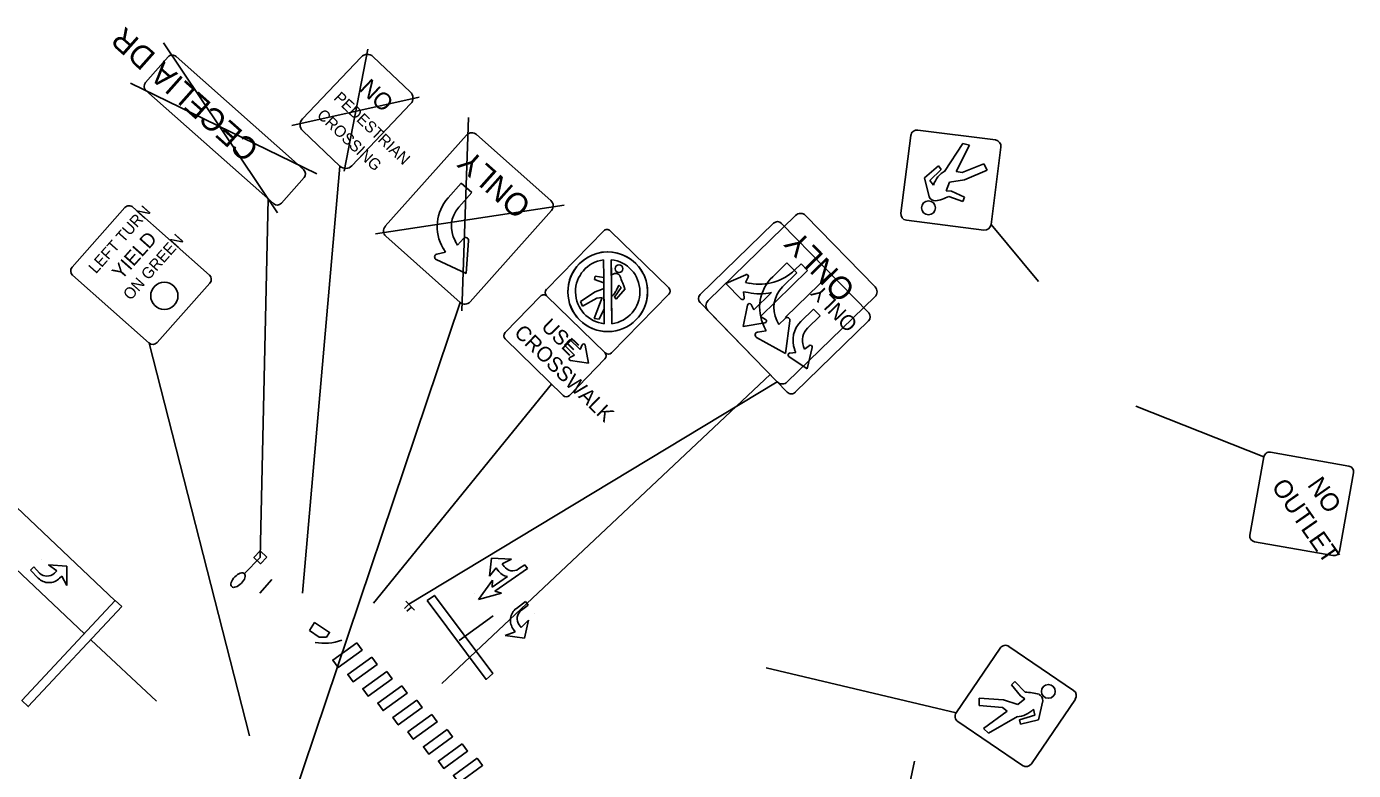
# Model space of a CAD drawing. Extents: x 1481212 to 1485683, y 378085 to 388655.
# Drawn here: x 1481389 to 1481680.9, y 378237 to 378400.7 of the extents above; entities that cross this region are included whole.
import ezdxf

# ---------------------------------------------------------------- set-up
doc = ezdxf.new("R2010")
doc.units = 0
for name, color, linetype in [('LT_X_Luminaires', 7, 'Continuous'), ('RS_Raster1', 7, 'Continuous'), ('RW_X_CL_100_Bearings', 7, 'Continuous'), ('RW_X_CL_100_Curve_Data', 7, 'Continuous'), ('RW_X_CL_100_Distances', 7, 'Continuous'), ('RW_X_CL_500_Cardinal_Points', 7, 'Continuous'), ('RW_X_CL_500_Distances', 7, 'Continuous'), ('RW_X_CL_500_Stations', 7, 'Continuous'), ('SC_Scratch1', 7, 'Continuous'), ('SC_Scratch15', 7, 'Continuous'), ('SC_Scratch8', 7, 'Continuous'), ('SN_P_Signs', 7, 'Continuous')]:
    doc.layers.add(name, color=color, linetype=linetype)

msp = doc.modelspace()

# ---------------------------------------------------------------- linework, layer by layer
at = {"layer": 'LT_X_Luminaires'}
msp.add_line((1481440.39, 378283.91), (1481436.89, 378280.33), dxfattribs=at)
msp.add_lwpolyline([(1481441.8, 378283.93), (1481440.4, 378282.5), (1481438.97, 378283.89), (1481440.37, 378285.32)], close=True, dxfattribs=at)
msp.add_ellipse((1481435.5, 378278.9), major_axis=(-1.4, -1.43), ratio=0.5, dxfattribs=at)
at = {"layer": 'RS_Raster1'}
for points in [[(1481461.59, 378265.13), (1481462.77, 378263.51), (1481457.5, 378259.69), (1481456.33, 378261.31)], [(1481464.9, 378261.96), (1481466.07, 378260.34), (1481460.81, 378256.53), (1481459.63, 378258.15)], [(1481468.2, 378258.8), (1481469.37, 378257.18), (1481464.11, 378253.37), (1481462.94, 378254.99)], [(1481471.5, 378255.63), (1481472.68, 378254.01), (1481467.41, 378250.2), (1481466.24, 378251.82)], [(1481474.81, 378252.47), (1481475.98, 378250.85), (1481470.72, 378247.04), (1481469.54, 378248.66)], [(1481478.11, 378249.31), (1481479.28, 378247.69), (1481474.02, 378243.87), (1481472.85, 378245.49)], [(1481481.52, 378246.04), (1481482.69, 378244.42), (1481477.43, 378240.61), (1481476.26, 378242.23)], [(1481484.82, 378242.88), (1481486, 378241.26), (1481480.73, 378237.45), (1481479.56, 378239.07)], [(1481488.13, 378239.72), (1481489.3, 378238.1), (1481484.04, 378234.28), (1481482.86, 378235.9)]]:
    msp.add_lwpolyline(points, close=True, dxfattribs=at)
at = {"layer": 'RW_X_CL_100_Bearings'}
msp.add_line((1481401.7, 378267.11), (1481366.27, 378300.56), dxfattribs=at)
at = {"layer": 'RW_X_CL_100_Curve_Data'}
for p, q in [((1481590.91, 378368.86), (1481594.96, 378375)), ((1481596.38, 378374.6), (1481593.48, 378368.85)), ((1481594.96, 378375), (1481596.38, 378374.6)), ((1481457.89, 378370.04), (1481449.67, 378276.05)), ((1481586.49, 378367.44), (1481589.59, 378370.09)), ((1481590.19, 378369.31), (1481587.68, 378366.86)), ((1481589.59, 378370.09), (1481590.19, 378369.31)), ((1481593.48, 378368.85), (1481594.78, 378368.6)), ((1481594.78, 378368.6), (1481599.53, 378370.53)), ((1481600.27, 378369.1), (1481595.29, 378366.99)), ((1481599.53, 378370.53), (1481600.27, 378369.1)), ((1481587.54, 378363.25), (1481586.49, 378367.44)), ((1481587.68, 378366.86), (1481588.48, 378365.83)), ((1481592.02, 378366.47), (1481591.25, 378364.62)), ((1481595.29, 378366.99), (1481592.02, 378366.47)), ((1481442.09, 378362.83), (1481440.37, 378283.9)), ((1481591.25, 378364.62), (1481592.43, 378364.53)), ((1481594.94, 378362.22), (1481591.87, 378363.34)), ((1481592.43, 378364.53), (1481595.27, 378363.22)), ((1481595.27, 378363.22), (1481594.94, 378362.22)), ((1481601.15, 378357.16), (1481611.55, 378344.64)), ((1481633.02, 378317.18), (1481661.17, 378306.04)), ((1481593.48, 378249.71), (1481551.67, 378259.6)), ((1481605.65, 378255.87), (1481606.39, 378256.62)), ((1481607.59, 378253.42), (1481605.65, 378255.87)), ((1481606.39, 378256.62), (1481608.62, 378254.22)), ((1481598.54, 378251.29), (1481598.53, 378252.9)), ((1481598.53, 378252.9), (1481603.92, 378252.52)), ((1481603.65, 378250.85), (1481598.54, 378251.29)), ((1481603.92, 378252.52), (1481607.07, 378251.5)), ((1481607.07, 378251.5), (1481608.6, 378252.8)), ((1481608.6, 378252.8), (1481607.59, 378253.42)), ((1481612.53, 378252.34), (1481611.56, 378248.13)), ((1481599.5, 378246.23), (1481604.69, 378250.04)), ((1481606.98, 378248.87), (1481600.58, 378245.23)), ((1481604.69, 378250.04), (1481603.65, 378250.85)), ((1481607.41, 378248.14), (1481610.77, 378249.19)), ((1481610.77, 378249.19), (1481610.52, 378250.47)), ((1481600.58, 378245.23), (1481599.5, 378246.23)), ((1481607.6, 378247.17), (1481607.41, 378248.14)), ((1481611.56, 378248.13), (1481607.6, 378247.17))]:
    msp.add_line(p, q, dxfattribs=at)
for points in [[(1481449.91, 378369.26), (1481421.87, 378394.15)], [(1481415.13, 378388.44), (1481420.11, 378394.05)], [(1481462.57, 378394.03), (1481449.66, 378380.43)], [(1481473.38, 378386.36), (1481465.22, 378394.1)], [(1481415.23, 378386.68), (1481443.27, 378361.78)], [(1481460.54, 378370.11), (1481473.45, 378383.71)], [(1481449.73, 378377.78), (1481457.89, 378370.04)], [(1481581.31, 378359.69), (1481583.48, 378376.75)], [(1481585.05, 378377.96), (1481602.11, 378375.79)], [(1481603.32, 378374.23), (1481601.15, 378357.16)], [(1481445.04, 378361.88), (1481450.02, 378367.49)], [(1481599.58, 378355.95), (1481582.52, 378358.12)], [(1481662.62, 378307.05), (1481679.84, 378303.98)], [(1481658.1, 378288.81), (1481661.17, 378306.04)], [(1481680.86, 378302.53), (1481677.79, 378285.3)], [(1481676.34, 378284.29), (1481659.11, 378287.36)], [(1481593.48, 378249.71), (1481603.15, 378263.93)], [(1481605.09, 378264.31), (1481619.32, 378254.64)], [(1481619.69, 378252.69), (1481610.02, 378238.47)], [(1481608.08, 378238.1), (1481593.85, 378247.76)]]:
    msp.add_lwpolyline(points, dxfattribs=at)
for centre in [(1481587.38, 378360.85), (1481613.75, 378254.41)]:
    msp.add_circle(centre, 1.52, dxfattribs=at)
for centre, radius, start, end in [((1481421.04, 378393.22), 1.25, 48.4, 138.4), ((1481463.93, 378392.74), 1.88, 46.5, 136.5), ((1481416.06, 378387.61), 1.25, 138.4, 228.4), ((1481472.09, 378385), 1.88, 316.5, 46.5), ((1481451.02, 378379.14), 1.88, 136.5, 226.5), ((1481584.87, 378376.57), 1.4, 82.7457, 172.7457), ((1481601.93, 378374.4), 1.4, 352.7457, 82.7457), ((1481449.08, 378368.32), 1.25, 318.4, 48.4), ((1481459.18, 378371.4), 1.88, 226.5, 316.5), ((1481593.84, 378364.07), 5.64, 119.5959, 161.8067), ((1481588.91, 378363.86), 1.5, 203.9899, 270.2407), ((1481587.35, 378371.92), 9.69, 279.2869, 297.7774), ((1481444.1, 378362.71), 1.25, 228.4, 318.4), ((1481582.7, 378359.51), 1.4, 172.7457, 262.7457), ((1481599.76, 378357.34), 1.4, 262.7457, 352.7457), ((1481662.4, 378305.82), 1.25, 79.9, 169.9), ((1481679.63, 378302.75), 1.25, 349.9, 79.9), ((1481659.33, 378288.59), 1.25, 169.9, 259.9), ((1481676.56, 378285.52), 1.25, 259.9, 349.9), ((1481604.31, 378263.15), 1.4, 55.8, 145.8), ((1481608.76, 378244.53), 9.69, 72.3411, 90.8317), ((1481618.53, 378253.48), 1.4, 325.8, 55.8), ((1481611.03, 378252.42), 1.5, 357.0441, 63.295), ((1481594.64, 378248.92), 1.4, 145.8, 235.8), ((1481606.54, 378254.47), 5.64, 272.6502, 314.8609), ((1481608.87, 378239.25), 1.4, 235.8, 325.8)]:
    msp.add_arc(centre, radius, start, end, dxfattribs=at)
at = {"layer": 'RW_X_CL_100_Distances'}
for p, q in [((1481392.21, 378283.43), (1481392.21, 378283.43)), ((1481490.83, 378279.78), (1481491.23, 378283.7)), ((1481491.23, 378283.7), (1481495.64, 378283.51)), ((1481495.64, 378283.51), (1481493.61, 378282.51)), ((1481497.92, 378283.26), (1481497.92, 378283.26)), ((1481390.54, 378281.8), (1481389.82, 378281.1)), ((1481389.82, 378281.1), (1481391.55, 378279.33)), ((1481391.84, 378280.46), (1481390.54, 378281.8)), ((1481397.82, 378281.97), (1481393.78, 378282.28)), ((1481393.78, 378282.28), (1481395.59, 378280.91)), ((1481395.59, 378280.91), (1481395.08, 378280.42)), ((1481397.79, 378277.7), (1481397.82, 378281.97)), ((1481492.29, 378281.6), (1481490.83, 378279.78)), ((1481499.15, 378281.48), (1481491.95, 378276.5)), ((1481492.67, 378281.05), (1481492.29, 378281.6)), ((1481493.61, 378282.51), (1481494.01, 378281.93)), ((1481497.2, 378281.35), (1481498.58, 378282.3)), ((1481498.58, 378282.3), (1481499.15, 378281.48)), ((1481396.23, 378279.3), (1481396.7, 378279.77)), ((1481396.7, 378279.77), (1481397.79, 378277.7)), ((1481397.79, 378277.7), (1481397.79, 378277.7)), ((1481488.38, 378274.64), (1481491.5, 378278.91)), ((1481491.5, 378278.91), (1481491.39, 378277.32)), ((1481487.43, 378276.01), (1481487.43, 378276.01)), ((1481493.48, 378276.05), (1481488.38, 378274.64)), ((1481491.95, 378276.5), (1481493.48, 378276.05)), ((1481498.71, 378274.16), (1481496.72, 378272.68)), ((1481497.82, 378272.25), (1481499.31, 378273.36)), ((1481499.31, 378273.36), (1481498.71, 378274.16)), ((1481497.77, 378268.47), (1481497.35, 378269.03)), ((1481499.36, 378270.08), (1481497.77, 378268.47)), ((1481498.52, 378266.12), (1481499.36, 378270.08)), ((1481500.7, 378271.49), (1481500.7, 378271.49)), ((1481496.49, 378267.51), (1481494.29, 378266.71)), ((1481494.29, 378266.71), (1481494.29, 378266.71)), ((1481494.29, 378266.71), (1481498.52, 378266.12)), ((1481496.09, 378268.05), (1481496.49, 378267.51))]:
    msp.add_line(p, q, dxfattribs=at)
msp.add_lwpolyline([(1481491.39, 378277.32), (1481494.76, 378279.66)], dxfattribs=at)
for centre, radius, start, end in [((1481393.48, 378282.07), 2.3, 224.2542, 314.2542), ((1481495.4, 378282.88), 3.28, 213.7589, 258.7139), ((1481495.9, 378283.24), 2.3, 214.6674, 304.6674), ((1481393.9, 378281.62), 3.28, 224.2542, 315.1627), ((1481498.69, 378270.05), 3.28, 126.7226, 217.6311), ((1481499.19, 378270.41), 2.3, 126.7226, 216.7226)]:
    msp.add_arc(centre, radius, start, end, dxfattribs=at)
at = {"layer": 'RW_X_CL_500_Cardinal_Points'}
msp.add_line((1481440.31, 378276.01), (1481442.89, 378279.07), dxfattribs=at)
msp.add_lwpolyline([(1481451.19, 378267.78), (1481452.32, 378269.55), (1481455.64, 378267.39), (1481454.95, 378266.33), (1481453.36, 378266.34)], close=True, dxfattribs=at)
msp.add_arc((1481454.46, 378276.11), 11.11, 259.501, 290.3578, dxfattribs=at)
at = {"layer": 'RW_X_CL_500_Distances'}
msp.add_line((1481373.57, 378307.38), (1481408.46, 378274.35), dxfattribs=at)
at = {"layer": 'RW_X_CL_500_Stations'}
for points in [[(1481477.11, 378274.42), (1481478.7, 378275.55), (1481491.54, 378258.34), (1481490.05, 378257.05)], [(1481409.9, 378273.06), (1481408.49, 378274.38), (1481387.93, 378252.37), (1481389.34, 378251.05)]]:
    msp.add_lwpolyline(points, close=True, dxfattribs=at)
at = {"layer": 'SC_Scratch1'}
msp.add_line((1481484.16, 378265.63), (1481491.62, 378271.03), dxfattribs=at)
at = {"layer": 'SC_Scratch15'}
for p, q in [((1481484.73, 378338.16), (1481486.22, 378380.72)), ((1481484.6, 378366.3), (1481481.69, 378363.04)), ((1481486.94, 378364.23), (1481484.6, 378366.3)), ((1481484.03, 378360.96), (1481486.94, 378364.23)), ((1481465.75, 378355.11), (1481507.23, 378361.42)), ((1481483.8, 378352.66), (1481483.29, 378353.51)), ((1481485.09, 378354.09), (1481483.8, 378352.66)), ((1481485.68, 378346.37), (1481486.18, 378353.63)), ((1481481.1, 378351.07), (1481479.22, 378350.63)), ((1481480.6, 378351.93), (1481481.1, 378351.07)), ((1481479.1, 378349.46), (1481485.68, 378346.37)), ((1481517.57, 378349.42), (1481517.74, 378335.34)), ((1481556.24, 378348.74), (1481553.11, 378345.69)), ((1481558.42, 378346.5), (1481556.24, 378348.74)), ((1481514.03, 378345.78), (1481513.91, 378345.08)), ((1481514.03, 378345.78), (1481513.91, 378345.08)), ((1481513.91, 378345.08), (1481515.95, 378344.36)), ((1481513.91, 378345.08), (1481515.95, 378344.36)), ((1481515.94, 378345.53), (1481514.03, 378345.78)), ((1481515.94, 378345.53), (1481514.03, 378345.78)), ((1481515.95, 378344.36), (1481515.95, 378344.59)), ((1481517.61, 378346.11), (1481517.62, 378345.96)), ((1481517.62, 378345.96), (1481517.67, 378341.4)), ((1481555.29, 378343.45), (1481558.42, 378346.5)), ((1481514.09, 378342.38), (1481510.86, 378340.26)), ((1481514.09, 378342.38), (1481510.86, 378340.26)), ((1481515.42, 378342.88), (1481514.09, 378342.38)), ((1481515.42, 378342.88), (1481514.09, 378342.38)), ((1481515.97, 378343.06), (1481515.42, 378342.88)), ((1481515.97, 378343.06), (1481515.42, 378342.88)), ((1481515.97, 378342.97), (1481515.97, 378343.06)), ((1481516.03, 378338.61), (1481515.97, 378342.97)), ((1481519.78, 378343.28), (1481518.28, 378341.21)), ((1481519.78, 378343.28), (1481518.28, 378341.21)), ((1481518.69, 378340.72), (1481520.62, 378343.02)), ((1481518.69, 378340.72), (1481520.62, 378343.02)), ((1481519.28, 378343.81), (1481519.78, 378343.28)), ((1481519.28, 378343.81), (1481519.78, 378343.28)), ((1481520.62, 378343.02), (1481520.61, 378343.04)), ((1481520.62, 378343.02), (1481520.61, 378343.04)), ((1481484.35, 378340.02), (1481446.53, 378227.66)), ((1481510.86, 378340.26), (1481511.24, 378339.17)), ((1481510.86, 378340.26), (1481511.24, 378339.17)), ((1481511.24, 378339.17), (1481514.45, 378340.97)), ((1481511.24, 378339.17), (1481514.45, 378340.97)), ((1481515.59, 378341.12), (1481513.85, 378336.51)), ((1481515.59, 378341.12), (1481513.85, 378336.51)), ((1481514.45, 378340.97), (1481515.59, 378341.12)), ((1481514.45, 378340.97), (1481515.59, 378341.12)), ((1481518.28, 378341.21), (1481518.69, 378340.72)), ((1481518.28, 378341.21), (1481518.69, 378340.72)), ((1481513.85, 378336.51), (1481514.96, 378336.37)), ((1481513.85, 378336.51), (1481514.96, 378336.37)), ((1481514.96, 378336.37), (1481516.03, 378338.61)), ((1481514.96, 378336.37), (1481516.03, 378338.61)), ((1481554.47, 378335.18), (1481554.03, 378336.07)), ((1481555.86, 378336.52), (1481554.47, 378335.18)), ((1481555.9, 378328.78), (1481556.91, 378335.98)), ((1481551.67, 378333.79), (1481549.76, 378333.49)), ((1481551.23, 378334.68), (1481551.67, 378333.79)), ((1481415.91, 378331.09), (1481438, 378244.65)), ((1481507.28, 378330.6), (1481508.51, 378331.85)), ((1481508.51, 378331.85), (1481510.71, 378329.7)), ((1481510.72, 378329.69), (1481511.22, 378330.7)), ((1481511.87, 378330.6), (1481512.61, 378326.62)), ((1481549.55, 378332.33), (1481555.9, 378328.78)), ((1481508.5, 378327.91), (1481509.49, 378328.44)), ((1481512.61, 378326.62), (1481508.61, 378327.27)), ((1481510.18, 378328.99), (1481510.18, 378328.99)), ((1481510.71, 378329.7), (1481510.72, 378329.69)), ((1481480.3, 378256.17), (1481552.58, 378324.13)), ((1481504.42, 378322.04), (1481465.29, 378273.84)), ((1481403.11, 378265.79), (1481417.55, 378252.23))]:
    msp.add_line(p, q, dxfattribs=at)
for points in [[(1481485.76, 378376.85), (1481467.89, 378356.78)], [(1481504.31, 378362.43), (1481487.97, 378376.98)], [(1481398.98, 378347.79), (1481410.6, 378360.88)], [(1481412.37, 378360.99), (1481429.19, 378346.05)], [(1481486.56, 378340.15), (1481504.43, 378360.22)], [(1481558.15, 378359.17), (1481538.89, 378340.43)], [(1481575.62, 378343.47), (1481560.36, 378359.14)], [(1481468.02, 378354.57), (1481484.35, 378340.02)], [(1481515.94, 378355.79), (1481503.37, 378342.9)], [(1481530.23, 378343.23), (1481517.35, 378355.8)], [(1481515.89, 378349.4), (1481515.93, 378345.57), (1481515.96, 378344.59), (1481515.95, 378344.59)], [(1481517.62, 378345.96), (1481517.57, 378349.42)], [(1481415.91, 378331.09), (1481399.09, 378346.03)], [(1481515.95, 378344.59), (1481515.94, 378345.53), (1481515.94, 378345.53)], [(1481515.95, 378344.59), (1481515.97, 378342.97), (1481516.04, 378337.73), (1481516.07, 378335.32)], [(1481517.74, 378335.34), (1481517.68, 378340.93), (1481517.68, 378340.93), (1481517.68, 378340.93), (1481517.62, 378345.96), (1481517.61, 378345.96)], [(1481517.62, 378345.96), (1481517.62, 378345.96)], [(1481429.3, 378344.28), (1481417.68, 378331.2)], [(1481517.68, 378328.93), (1481530.25, 378341.82)], [(1481502.05, 378341.41), (1481494.22, 378333.38)], [(1481503.38, 378341.49), (1481516.26, 378328.92)], [(1481516.2, 378328.98), (1481503.45, 378341.42)], [(1481556.33, 378322.51), (1481575.59, 378341.26)], [(1481538.86, 378338.22), (1481554.12, 378322.54)], [(1481494.24, 378331.98), (1481506.98, 378319.54)], [(1481509.48, 378328.44), (1481507.28, 378330.6)], [(1481508.38, 378319.56), (1481516.21, 378327.59)]]:
    msp.add_lwpolyline(points, dxfattribs=at)
for centre, radius in [((1481516.82, 378342.37), 8.77), ((1481519.3, 378347.45), 0.864), ((1481419.27, 378341.48), 3)]:
    msp.add_circle(centre, radius, dxfattribs=at)
for centre, radius, start, end in [((1481486.93, 378375.81), 1.56, 48.3134, 138.3134), ((1481488.77, 378356.73), 9.48, 138.3134, 210.4559), ((1481503.27, 378361.26), 1.56, 318.3134, 48.3134), ((1481411.54, 378360.05), 1.25, 48.4, 138.4), ((1481488.77, 378356.73), 6.35, 138.3134, 210.4521), ((1481559.24, 378358.05), 1.56, 44.232, 134.232), ((1481469.06, 378355.74), 1.56, 138.3134, 228.3134), ((1481485.56, 378353.67), 0.625, 356.0677, 137.8394), ((1481516.65, 378355.09), 1, 45.6945, 135.6945), ((1481479.36, 378350.03), 0.625, 103.107, 244.8787), ((1481516.82, 378342.37), 8.77, 315.6945, 135.6945), ((1481399.92, 378346.96), 1.25, 138.4, 228.4), ((1481516.82, 378342.37), 8.77, 135.6945, 315.6945), ((1481516.82, 378342.37), 7.09, 97.5424, 263.9425), ((1481516.82, 378342.37), 7.09, 97.5424, 263.9425), ((1481516.82, 378342.37), 7.09, 277.5136, 83.8658), ((1481516.82, 378342.37), 7.09, 277.5136, 83.8658), ((1481428.36, 378345.11), 1.25, 318.4, 48.4), ((1481517.82, 378344.44), 1.54, 97.7697, 97.8228), ((1481559.72, 378338.89), 9.48, 134.232, 206.3745), ((1481502.76, 378340.72), 0.989, 45.6945, 135.6945), ((1481504.08, 378342.21), 1, 135.6945, 225.6945), ((1481529.54, 378342.51), 1, 315.6945, 45.6945), ((1481559.72, 378338.89), 6.35, 134.232, 206.3707), ((1481574.5, 378342.38), 1.56, 314.232, 44.232), ((1481485.39, 378341.19), 1.56, 228.3134, 318.3134), ((1481539.98, 378339.31), 1.56, 134.232, 224.232), ((1481556.29, 378336.07), 0.625, 351.9863, 133.758), ((1481494.93, 378332.69), 0.989, 135.6945, 225.6945), ((1481549.86, 378332.87), 0.625, 99.0256, 240.7973), ((1481416.74, 378332.03), 1.25, 228.4, 318.4), ((1481511.53, 378330.54), 0.342, 10.6152, 153.3323), ((1481508.66, 378327.61), 0.342, 118.0567, 260.7737), ((1481515.5, 378328.28), 0.989, 315.6945, 45.6945), ((1481516.96, 378329.63), 1, 225.6945, 315.6945), ((1481555.24, 378323.63), 1.56, 224.232, 314.232), ((1481507.67, 378320.25), 0.989, 225.6945, 315.6945)]:
    msp.add_arc(centre, radius, start, end, dxfattribs=at)
for points in [[(1481520.61, 378343.04), (1481520.25, 378343.93), (1481519.7, 378345.35), (1481519.49, 378345.88), (1481519.4, 378346.02), (1481519.28, 378346.14), (1481518.99, 378346.42), (1481518.3, 378346.43), (1481517.88, 378346.23), (1481517.61, 378346.11)], [(1481520.61, 378343.04), (1481520.25, 378343.93), (1481519.7, 378345.35), (1481519.49, 378345.88), (1481519.4, 378346.02), (1481519.28, 378346.14), (1481518.99, 378346.42), (1481518.3, 378346.43), (1481517.88, 378346.23), (1481517.61, 378346.11)], [(1481517.67, 378341.4), (1481517.74, 378341.43), (1481517.93, 378341.53), (1481518.23, 378341.89), (1481518.46, 378342.24), (1481518.82, 378342.9), (1481519.06, 378343.36), (1481519.28, 378343.81)], [(1481517.67, 378341.4), (1481517.74, 378341.43), (1481517.93, 378341.53), (1481518.23, 378341.89), (1481518.46, 378342.24), (1481518.82, 378342.9), (1481519.06, 378343.36), (1481519.28, 378343.81)]]:
    msp.add_open_spline(points, degree=3, dxfattribs=at)
at = {"layer": 'SC_Scratch8'}
for p, q in [((1481559.35, 378348.53), (1481557.93, 378347.15)), ((1481560.8, 378347.04), (1481559.35, 378348.53)), ((1481547.21, 378346.13), (1481542.77, 378344.21)), ((1481547.12, 378344.42), (1481547.74, 378345.55)), ((1481550.4, 378336.91), (1481560.8, 378347.04)), ((1481555.95, 378336.79), (1481565.81, 378346.38)), ((1481542.77, 378344.21), (1481546.15, 378340.75)), ((1481546.87, 378341.09), (1481546.72, 378342.37)), ((1481546.72, 378342.37), (1481547.71, 378342.18)), ((1481548.11, 378344.22), (1481547.12, 378344.42)), ((1481552.85, 378342.2), (1481548.95, 378338.4)), ((1481547.59, 378339.45), (1481546.64, 378334.7)), ((1481548.95, 378338.4), (1481548.37, 378339.55)), ((1481551.54, 378336.3), (1481550.4, 378336.91)), ((1481559.33, 378335.86), (1481562.09, 378338.55)), ((1481563.54, 378337.06), (1481560.78, 378334.37)), ((1481562.09, 378338.55), (1481563.54, 378337.06)), ((1481546.64, 378334.7), (1481551.41, 378335.52)), ((1481559.89, 378330.35), (1481560.14, 378329.71)), ((1481560.14, 378329.71), (1481561.15, 378330.5)), ((1481561.81, 378330.08), (1481560.66, 378325.38)), ((1481560.66, 378325.38), (1481556.69, 378328.13)), ((1481556.9, 378328.89), (1481558.19, 378328.97)), ((1481558.19, 378328.97), (1481557.94, 378329.61)), ((1481554.12, 378322.54), (1481473.08, 378273.58)), ((1481473.08, 378273.58), (1481472.09, 378272.66)), ((1481472.43, 378274.28), (1481474.29, 378272.29)), ((1481473.64, 378272.98), (1481472.64, 378272.06)), ((1481473.36, 378273.28), (1481473.36, 378273.28)), ((1481473.36, 378273.28), (1481473.36, 378273.28))]:
    msp.add_line(p, q, dxfattribs=at)
for points in [[(1481553.28, 378357.45), (1481537.16, 378341.76)], [(1481574.23, 378337.72), (1481555.05, 378357.43)], [(1481537.14, 378339.99), (1481556.32, 378320.28)], [(1481558.09, 378320.26), (1481574.21, 378335.96)]]:
    msp.add_lwpolyline(points, dxfattribs=at)
for centre, radius, start, end in [((1481554.16, 378356.55), 1.25, 44.232, 134.232), ((1481547.37, 378345.75), 0.417, 331.5722, 113.4504), ((1481550.23, 378355.06), 11.04, 258.9341, 314.232), ((1481538.03, 378340.86), 1.25, 134.232, 224.232), ((1481550.23, 378355.06), 13.13, 258.9341, 281.5064), ((1481546.45, 378341.05), 0.417, 224.4178, 6.2959), ((1481548, 378339.36), 0.417, 26.8701, 168.7483), ((1481551.34, 378335.93), 0.417, 279.7157, 61.5938), ((1481563.4, 378331.68), 5.83, 134.232, 200.766), ((1481573.34, 378336.85), 1.25, 314.232, 44.232), ((1481563.4, 378331.68), 3.75, 134.232, 200.766), ((1481561.41, 378330.18), 0.417, 346.2497, 128.1278), ((1481556.93, 378328.48), 0.417, 93.4041, 235.2823), ((1481557.22, 378321.16), 1.25, 224.232, 314.232)]:
    msp.add_arc(centre, radius, start, end, dxfattribs=at)
at = {"layer": 'SN_P_Signs'}
for p, q in [((1481444.18, 378359.72), (1481419.06, 378397.17)), ((1481458.81, 378368.9), (1481464.02, 378395.79)), ((1481411.85, 378388.28), (1481452.81, 378368.3)), ((1481475.37, 378385.22), (1481447.32, 378378.99)), ((1481573.66, 378188.63), (1481584.3, 378239.04))]:
    msp.add_line(p, q, dxfattribs=at)

# ---------------------------------------------------------------- texts
at = {"layer": 'RW_X_CL_100_Curve_Data'}
for s, height, rotation, p in [('       CECELIA DR', 5, 138.4, (1481450.17, 378365.68)), ('NO', 3.75, 316.5, (1481461.98, 378386.84)), ('PEDESTRIAN', 2.5, 316.5, (1481456.38, 378384.82)), ('CROSSING', 2.5, 316.5, (1481452.67, 378381.02)), ('OUTLET', 4, 304.9, (1481662.7, 378299.49)), ('NO', 4, 304.9, (1481670.59, 378299.83))]:
    msp.add_text(s, height=height, rotation=rotation, dxfattribs=at).set_placement(p)
at = {"layer": 'SC_Scratch15'}
for s, height, rotation, p in [('ONLY', 5, 138.3134, (1481500.29, 378361.82)), ('LEFT TURN', 2.503, 48.4, (1481404.22, 378346.19)), ('YIELD', 3.128, 48.4, (1481409.84, 378344.83)), ('ON GREEN', 2.503, 48.4, (1481411.84, 378340.33)), ('ONLY', 5, 134.232, (1481571.57, 378343.15)), ('USE', 3.296, 315.6945, (1481501.99, 378334.45)), ('CROSSWALK', 3.296, 315.6945, (1481496.02, 378333.1))]:
    msp.add_text(s, height=height, rotation=rotation, dxfattribs=at).set_placement(p)
at = {"layer": 'SC_Scratch8'}
msp.add_text('ONLY', height=3.333, rotation=134.232, dxfattribs=at).set_placement((1481572.02, 378335.52))

doc.saveas('drawing.dxf')
